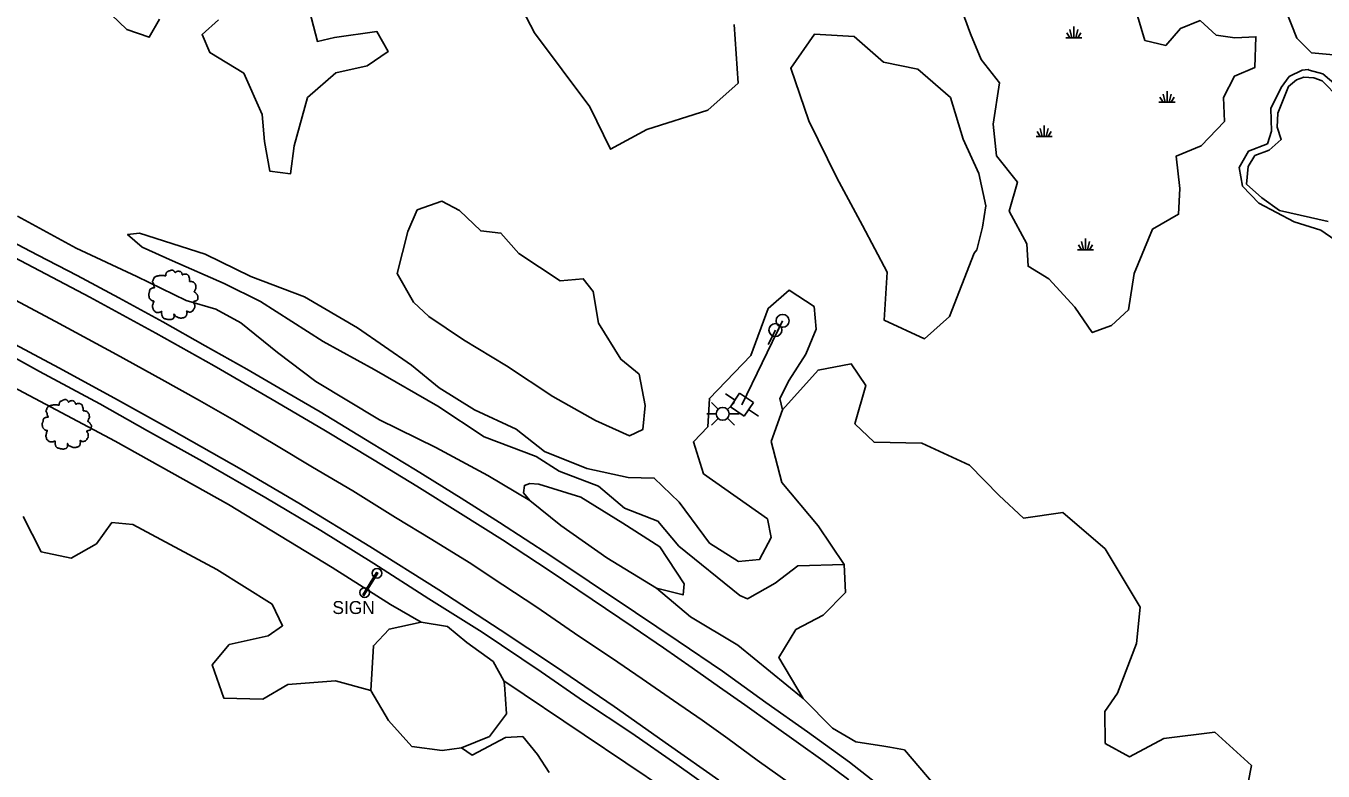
# Model space of a CAD drawing. Extents: x 2160437 to 2172832, y 205694 to 212444.
# Drawn here: x 2170821.8 to 2171222.4, y 207237.9 to 207468 of the extents above; entities that cross this region are included whole.
import ezdxf

# ---------------------------------------------------------------- set-up
doc = ezdxf.new("R2010")
doc.units = 0
for name, color, linetype in [('Default', 7, 'Continuous'), ('RD_EX_Bldg_Signs', 7, 'Continuous'), ('RD_EX_BldgApp_txCode', 7, 'Continuous'), ('RD_EX_H2O_Pond', 7, 'Continuous'), ('RD_EX_H2O_WetLd', 7, 'Continuous'), ('RD_EX_LaneStripe', 7, 'Continuous'), ('RD_EX_Road', 7, 'Continuous'), ('RD_EX_Road_Post', 7, 'Continuous'), ('RD_EX_UT', 7, 'Continuous'), ('RD_EX_UT_Guy', 7, 'Continuous'), ('RD_EX_VEG', 7, 'Continuous'), ('RD_EX_VEG_ShrubLine', 7, 'Continuous'), ('RD_EX_VEG_TreeLine', 7, 'Continuous')]:
    doc.layers.add(name, color=color, linetype=linetype)

# ---------------------------------------------------------------- blocks, each defined once
blk = doc.blocks.new('MARSH')
at = {"layer": 'Default'}
for points in [[(-0.0417, 0), (0.0417, 0)], [(-0.0365, 0.026), (-0.0208, 0)], [(-0.0104, 0), (-0.0208, 0.0417)], [(0, 0.0573), (0, 0)], [(0.0104, 0), (0.0208, 0.0417)], [(0.0365, 0.026), (0.0208, 0)]]:
    blk.add_lwpolyline(points, dxfattribs=at)
blk = doc.blocks.new('POST')
at = {"layer": 'Default'}
for start, end in [(90, 270), (270, 90)]:
    blk.add_arc((0, 0), 0.0417, start, end, dxfattribs=at)
blk = doc.blocks.new('T2')
at = {"layer": 'RD_EX_VEG'}
for points in [[(0.05, 7.21), (-0.25, 7.24), (-0.57, 7.14), (-0.82, 7.04), (-1.05, 6.96), (-1.27, 6.86), (-1.57, 6.69), (-1.8, 6.49), (-1.92, 6.24), (-1.97, 6.01), (-2.02, 5.74), (-2.02, 5.56), (-2.15, 5.54), (-2.3, 5.56), (-2.55, 5.64), (-2.8, 5.64), (-3.05, 5.64), (-3.4, 5.61), (-3.75, 5.61), (-4.02, 5.56), (-4.35, 5.51), (-4.72, 5.39), (-5.07, 5.26), (-5.37, 5.01), (-5.62, 4.54), (-5.75, 4.19), (-5.9, 3.94), (-5.75, 3.49), (-5.57, 3.14), (-5.55, 2.94), (-5.47, 2.52), (-5.37, 2.29), (-5.25, 2.09), (-5.32, 2.07), (-5.7, 2.02), (-6, 1.92), (-6.42, 1.69), (-6.64, 1.47), (-6.74, 1.14), (-6.77, 0.79), (-6.87, 0.59), (-6.94, 0.32), (-6.97, 0.24), (-7.02, -0.08), (-6.92, -0.53), (-6.89, -0.88), (-6.77, -1.11), (-6.62, -1.28), (-6.44, -1.53), (-6.05, -1.76), (-5.72, -1.86), (-5.52, -1.88), (-5.7, -2.38), (-5.75, -2.73), (-5.87, -3.13), (-5.87, -3.21), (-5.92, -3.68), (-5.77, -4.01), (-5.7, -4.38), (-5.52, -4.61), (-5.25, -4.91), (-4.92, -5.13), (-4.42, -5.26), (-4.02, -5.23), (-3.45, -5.06), (-3.2, -4.98), (-3.22, -5.16), (-3.2, -5.53), (-3.2, -5.96), (-3.05, -6.28), (-2.95, -6.56), (-2.8, -6.81), (-2.47, -7.03), (-2.07, -7.11), (-1.65, -7.26), (-1.2, -7.33), (-0.7, -7.36), (-0.1, -7.21), (0.18, -7.08), (0.28, -6.91), (0.48, -6.53), (0.43, -6.31), (0.45, -5.71), (0.55, -5.88), (0.73, -6.23), (1.23, -6.53), (1.63, -6.71), (2.1, -6.86), (2.4, -6.93), (2.88, -6.86), (3.25, -6.78), (3.63, -6.66), (3.93, -6.38), (4.1, -6.11), (4.15, -5.83), (4.23, -5.46), (4.28, -5.28)], [(4.28, -5.28), (4.2, -5.11), (4.15, -4.86), (4.23, -4.88), (4.4, -4.93), (4.68, -5.06), (4.9, -5.13), (5.23, -5.11), (5.5, -5.01), (5.95, -4.73), (6.22, -4.26), (6.5, -3.86), (6.57, -3.53), (6.52, -3.31), (6.5, -2.81), (6.3, -2.56), (6.25, -2.43), (6.15, -2.03), (6.22, -1.98), (6.5, -1.93), (6.87, -1.81), (7.15, -1.68), (7.37, -1.51), (7.45, -1.28), (7.42, -0.88), (7.47, -0.48), (7.4, -0.33), (7.3, -0.18), (7.22, 0.02), (7.07, 0.17), (6.97, 0.32), (6.87, 0.42), (6.75, 0.57), (6.57, 0.69), (6.42, 0.74), (6.37, 0.89), (6.52, 1.09), (6.57, 1.19), (6.6, 1.42), (6.82, 1.77), (6.87, 2.17), (6.82, 2.59), (6.77, 2.87), (6.62, 3.14), (6.42, 3.39), (6.3, 3.56), (6.12, 3.69), (5.8, 3.81), (5.55, 3.86), (5.2, 3.86), (5, 3.91), (5.03, 3.96), (5.03, 4.11), (5.03, 4.39), (4.95, 4.84), (4.8, 5.34), (4.8, 5.36), (4.7, 5.61), (4.48, 5.81), (4.3, 5.91), (4.1, 6.04), (3.85, 6.06), (3.55, 6.06), (3.28, 6.01), (3.08, 5.91), (2.9, 5.79), (2.83, 5.94), (2.73, 6.24), (2.68, 6.39), (2.53, 6.56), (2.3, 6.76), (1.85, 6.89), (1.23, 6.81), (0.93, 6.61), (0.78, 6.44), (0.73, 6.56), (0.53, 6.76), (0.43, 6.94), (0.25, 7.06), (0.1, 7.16), (0, 7.21)]]:
    blk.add_spline(points, degree=3, dxfattribs=at)
blk = doc.blocks.new('PP')
at = {"layer": 'RD_EX_UT'}
for p, q in [((2.49, 2.51), (-2.51, 2.51)), ((-2.51, 2.51), (-2.51, -2.49)), ((2.49, -2.49), (2.49, 2.51)), ((-5.94, -0.05), (-2.47, -0.05)), ((-2.51, -2.49), (2.49, -2.49)), ((2.42, -0.05), (6.06, -0.05))]:
    blk.add_line(p, q, dxfattribs=at)

msp = doc.modelspace()

# ---------------------------------------------------------------- linework, layer by layer
at = {"layer": 'RD_EX_Bldg_Signs'}
msp.add_lwpolyline([(2170925.78, 207292.33), (2170930.07, 207299.26), (2170930.43, 207299.03), (2170926.14, 207292.1)], close=True, dxfattribs=at)
at = {"layer": 'RD_EX_H2O_Pond'}
msp.add_lwpolyline([(2171223.91, 207407.61), (2171215.24, 207409.62), (2171208.89, 207411.01), (2171203.41, 207414.96), (2171198.75, 207419.15), (2171199.26, 207424.58), (2171201.33, 207427.96), (2171205.76, 207429.6), (2171209.43, 207432.91), (2171208.23, 207436.73), (2171208.42, 207441.03), (2171211.72, 207449.31), (2171214.19, 207451.34), (2171216.38, 207452.22), (2171219.54, 207451.99), (2171222.12, 207451.05), (2171227.31, 207445.7)], dxfattribs=at)
at = {"layer": 'RD_EX_H2O_WetLd'}
msp.add_lwpolyline([(2171165.1, 207471.1), (2171167.33, 207463.54), (2171173.77, 207462), (2171178.29, 207467.17), (2171184.43, 207469.65), (2171189.31, 207465.16), (2171195.14, 207464.31), (2171201.64, 207464.68), (2171201.24, 207455.17), (2171195.02, 207452.52), (2171191.58, 207445.94), (2171191.95, 207438.52), (2171184.72, 207431.03), (2171176.98, 207427.76), (2171178.13, 207417.84), (2171177.73, 207409.86), (2171169.7, 207405.28), (2171164, 207391.58), (2171162.29, 207380.32), (2171157.01, 207375.5), (2171151.1, 207373.32), (2171145.71, 207381.12), (2171137.63, 207389.94), (2171131.24, 207393.8), (2171130.85, 207400.72), (2171125.38, 207410.79), (2171127.96, 207419.71), (2171121.51, 207427.88), (2171120.49, 207437.64), (2171122.41, 207450.44), (2171116.74, 207457.64), (2171113.46, 207465.58), (2171110.54, 207473.66)], dxfattribs=at)
at = {"layer": 'RD_EX_LaneStripe'}
msp.add_lwpolyline([(2171057.86, 207233.96), (2171047.6, 207241.26), (2171038.51, 207247.92), (2171030.59, 207253.61), (2171021.8, 207259.72), (2171012.07, 207266.37), (2171002.66, 207272.85), (2170992.52, 207279.61), (2170979.54, 207288.55), (2170969.07, 207295.46), (2170958.61, 207302.27), (2170947.11, 207309.45), (2170935.95, 207316.25), (2170922.71, 207324.46), (2170910.32, 207331.8), (2170899.11, 207338.44), (2170886.22, 207346.19), (2170875.4, 207352.34), (2170863.78, 207358.8), (2170849.7, 207366.58), (2170830.89, 207376.77), (2170813.63, 207385.89)], dxfattribs=at)
at = {"layer": 'RD_EX_Road'}
for points in [[(2170808.45, 207406.07), (2170825.44, 207397.2), (2170837.58, 207390.92), (2170850.5, 207384.07), (2170864.02, 207376.63), (2170877.12, 207369.22), (2170889.95, 207362.01), (2170902.31, 207354.81), (2170912.64, 207348.83), (2170928.5, 207339.2), (2170942.09, 207330.88), (2170956.16, 207322.13), (2170968.04, 207314.62), (2170983.89, 207304.38), (2170995.75, 207296.45), (2171010.07, 207286.92), (2171023.21, 207277.99), (2171036.87, 207268.74), (2171050.24, 207259.11), (2171063.11, 207249.97), (2171076.1, 207240.67), (2171088.07, 207231.3)], [(2171075.94, 207235.22), (2171067.86, 207241.12), (2171060.32, 207246.47), (2171052.16, 207252.42), (2171043.77, 207258.41), (2171035.98, 207263.83), (2171027.56, 207269.77), (2171018.68, 207275.93), (2171009.33, 207282.38), (2170996.62, 207290.91), (2170983.36, 207299.8), (2170968.91, 207309.31), (2170955.96, 207317.49), (2170942.47, 207325.88), (2170929.31, 207333.95), (2170913.76, 207343.33), (2170897.77, 207352.68), (2170879.89, 207363.06), (2170861.87, 207373.14), (2170841.46, 207384.23), (2170826.06, 207392.41), (2170814.1, 207398.63)], [(2171037.38, 207229.55), (2171022.79, 207239.97), (2171008.84, 207249.58), (2170993.99, 207259.51), (2170980.86, 207268.51), (2170962.71, 207280.75), (2170946.19, 207291.09), (2170929.18, 207302.03), (2170912.88, 207312.19), (2170895.9, 207322.26), (2170876.18, 207333.58), (2170859.37, 207343.01), (2170844.59, 207351.26), (2170825.93, 207361.34), (2170810.8, 207369.66)], [(2171035.72, 207235.06), (2171020.23, 207246.05), (2171003.43, 207257.84), (2170985.33, 207270.23), (2170968.27, 207281.56), (2170949.32, 207293.83), (2170928.01, 207307.24), (2170906.06, 207320.59), (2170888.35, 207331.06), (2170866.72, 207343.32), (2170849.15, 207353.05), (2170831.97, 207362.41), (2170813.73, 207372.06)]]:
    msp.add_lwpolyline(points, dxfattribs=at)
at = {"layer": 'RD_EX_UT'}
for p, q in [((2171053.23, 207374.09), (2171051.02, 207369.6)), ((2171055.46, 207376.94), (2171053.26, 207372.45)), ((2171033.48, 207351.77), (2171035.58, 207349.68)), ((2171038.39, 207349.61), (2171040.56, 207351.77)), ((2171034.95, 207348.24), (2171032.02, 207348.24)), ((2171033.48, 207344.7), (2171035.56, 207346.78)), ((2171038.41, 207346.85), (2171040.56, 207344.7)), ((2171042.02, 207348.24), (2171038.95, 207348.24))]:
    msp.add_line(p, q, dxfattribs=at)
for centre in [(2171055.46, 207376.94), (2171053.23, 207374.09), (2171036.95, 207348.22)]:
    msp.add_circle(centre, 2, dxfattribs=at)
at = {"layer": 'RD_EX_UT_Guy'}
msp.add_lwpolyline([(2171055.46, 207376.94), (2171042.88, 207351.03)], dxfattribs=at)
at = {"layer": 'RD_EX_VEG_ShrubLine'}
for points in [[(2170843.29, 207476.3), (2170852.96, 207466.95), (2170859.84, 207464.5), (2170863.05, 207470.14)], [(2170881.27, 207469.94), (2170876.17, 207465.35), (2170878.56, 207459.76), (2170889.1, 207453.38), (2170894.69, 207440.69), (2170895.42, 207432.3), (2170897.12, 207423.14), (2170903.49, 207422.35), (2170904.62, 207431.02), (2170908.71, 207445.87), (2170917.43, 207453.5), (2170927.19, 207455.64), (2170933.62, 207460.07), (2170930.15, 207466.24), (2170917.1, 207464.41), (2170911.79, 207463.2), (2170911.79, 207463.2), (2170908.69, 207475.04)], [(2171228.44, 207447.99), (2171222.3, 207453.17), (2171218.09, 207454.34), (2171217.8, 207454.53), (2171215.89, 207454.38), (2171211.85, 207452.36), (2171209.39, 207449.01), (2171206.21, 207442.56), (2171206.46, 207435.56), (2171205.15, 207431.61), (2171199.31, 207429.35), (2171196.41, 207424.26), (2171197.44, 207418.53), (2171202.51, 207413.23), (2171213.42, 207407.55), (2171221.67, 207404.97), (2171226, 207401.96)], [(2170977.35, 207321.43), (2170964.45, 207329.21), (2170948.37, 207337.84), (2170931, 207346.34), (2170911.35, 207358.2), (2170899.49, 207367.13), (2170888.14, 207376.29), (2170880.39, 207380.52), (2170871.22, 207383.21), (2170856.06, 207390.65), (2170837.26, 207399.36), (2170819.16, 207409.27)], [(2171055.47, 207349.5), (2171054.58, 207352.91), (2171057.43, 207358.64), (2171062.65, 207366.65), (2171065.81, 207374.4), (2171065.23, 207381.35), (2171057.43, 207386.36), (2171050.98, 207380.76), (2171045.59, 207366.19), (2171032.87, 207352.97), (2171032.32, 207344.24), (2171027.91, 207339.53), (2171031.04, 207329.72), (2171050.74, 207315.75), (2171051.88, 207310.02), (2171048.36, 207303.27), (2171041.83, 207302.6), (2171032.9, 207308.24), (2171023.53, 207320.93), (2171015.82, 207328.36), (2171007.76, 207328.59), (2170995.02, 207331.3), (2170981.87, 207336.64), (2170973.18, 207343.5), (2170960.3, 207349.43), (2170949.37, 207356.3), (2170940.85, 207363.28), (2170924.22, 207374.82), (2170907.77, 207384.33), (2170891.27, 207390.61), (2170877.11, 207397.53), (2170856.82, 207404.02), (2170853.18, 207403.65), (2170857.7, 207399.73), (2170867.05, 207395.43), (2170883.04, 207388.47), (2170894.17, 207382.94), (2170913.57, 207370.54), (2170929.28, 207361.87), (2170948.98, 207350.56), (2170963.3, 207341.1), (2170979.3, 207335.06), (2170986.42, 207330.56), (2170998.56, 207325.89), (2171006.66, 207319.1), (2171016.95, 207315.07), (2171023.42, 207307.4), (2171042.21, 207292.12), (2171044.61, 207291.11), (2171053.16, 207295.95), (2171060.13, 207301.32), (2171074.51, 207301.74)], [(2170816.16, 207357.35), (2170849.29, 207339.83), (2170884.36, 207320.21), (2170916.34, 207300.79), (2170934.34, 207289.34), (2170943.81, 207283.92)], [(2170928.27, 207262.8), (2170917.39, 207265.77), (2170902.65, 207264.59), (2170894.96, 207260.07), (2170882.88, 207260.43), (2170879.27, 207270.76), (2170884.58, 207276.99), (2170896.61, 207279.62), (2170901.03, 207282.79), (2170897.79, 207289.49), (2170880.77, 207300.18), (2170854.81, 207314.08), (2170848.32, 207314.62), (2170843.59, 207308.12), (2170835.73, 207303.67), (2170826.5, 207305.58), (2170820.92, 207316.51)], [(2171061.77, 207260.34), (2171041.62, 207276.77), (2171026.99, 207285.55), (2171016.49, 207294.38)], [(2170969.33, 207265.74), (2170994.22, 207249.07), (2171019.95, 207231.81), (2171057.1, 207204.29), (2171086.49, 207181.68), (2171124.11, 207152.31), (2171171.23, 207114.4), (2171189.11, 207100.25), (2171205.42, 207087.84)], [(2170983.36, 207237.51), (2170979.78, 207243.04), (2170975.2, 207248.62), (2170969.86, 207248.32), (2170959.58, 207242.83), (2170956.26, 207245.11)]]:
    msp.add_lwpolyline(points, dxfattribs=at)
msp.add_lwpolyline([(2170936.45, 207391.56), (2170941.47, 207382.72), (2170946.17, 207378.26), (2170956.86, 207371.1), (2170970.18, 207363.02), (2170984.51, 207353.57), (2170997.65, 207346.19), (2171008.21, 207341.41), (2171012.29, 207343.41), (2171013.05, 207350.82), (2171011.16, 207360.46), (2171005.54, 207365.09), (2170998.63, 207376.24), (2170996.99, 207385.98), (2170993.91, 207389.94), (2170986.8, 207389.34), (2170974.04, 207397.77), (2170968.44, 207404.02), (2170962.24, 207404.73), (2170955.65, 207411.03), (2170950.23, 207413.94), (2170942.63, 207411.17), (2170939.68, 207404.56)], close=True, dxfattribs=at)
at = {"layer": 'RD_EX_VEG_TreeLine'}
for points in [[(2171040.52, 207468.48), (2171041.77, 207450.35), (2171032.41, 207442), (2171013.52, 207436), (2171002.35, 207429.92), (2170995.95, 207443.07), (2170978.87, 207465.84), (2170963.84, 207494.81)], [(2171112.04, 207222.22), (2171093.07, 207244.46), (2171088.56, 207245.32), (2171086.73, 207245.59), (2171078.05, 207246.93), (2171070.82, 207251.18), (2171061.77, 207260.34), (2171054.32, 207272.96), (2171059.51, 207281.59), (2171068, 207286.06), (2171074.87, 207293), (2171074.51, 207301.74), (2171066.41, 207313.64), (2171055.23, 207327.05), (2171051.96, 207339.68), (2171055.47, 207349.5), (2171066.4, 207361.72), (2171076.67, 207363.62), (2171081.15, 207356.97), (2171077.76, 207345.16), (2171083.71, 207339.46), (2171098.49, 207339.19), (2171113.19, 207332.32), (2171122.36, 207322.99), (2171129.89, 207316.05), (2171141.99, 207317.73), (2171155.09, 207306.49), (2171165.86, 207288.48), (2171164.78, 207277.26), (2171158.84, 207261.93), (2171155, 207256.25), (2171155.07, 207246.42), (2171162.58, 207242.34), (2171173.15, 207247.99), (2171188.97, 207249.9), (2171200.24, 207239.66), (2171198.12, 207228.59)]]:
    msp.add_lwpolyline(points, dxfattribs=at)
for points in [[(2171232.53, 207465.24), (2171226.68, 207458.95), (2171218.77, 207459.74), (2171214.23, 207464.28), (2171210.71, 207473.04), (2171213.77, 207479.7), (2171219.36, 207482.74), (2171224.84, 207481.34), (2171228.31, 207478.01), (2171230.37, 207474.3), (2171232.59, 207468.68), (2171232.58, 207466.24)], [(2171114.56, 207397.85), (2171106.98, 207378.27), (2171099.32, 207371.39), (2171086.85, 207377.13), (2171087.78, 207392.01), (2171080.1, 207406.37), (2171072.16, 207421.05), (2171063.55, 207438.69), (2171057.97, 207454.94), (2171065.26, 207465.46), (2171077.57, 207464.7), (2171086.61, 207456.86), (2171097.22, 207454.62), (2171107.29, 207445.9), (2171111.19, 207433.09), (2171116.09, 207422.46), (2171118.24, 207412.49), (2171117.21, 207405.82), (2171115.44, 207398.87)], [(2170980.15, 207326.53), (2170993.18, 207322.47), (2171006.14, 207314.46), (2171017.57, 207307.15), (2171025.07, 207295.74), (2171024.73, 207292.32), (2171016.49, 207294.38), (2171001.21, 207303.77), (2170987.01, 207313.71), (2170977.35, 207321.43), (2170975.42, 207323.87), (2170975.74, 207326.13), (2170977.42, 207326.68)], [(2170969.53, 207264.62), (2170970.15, 207255.56), (2170964.9, 207248.58), (2170956.26, 207245.11), (2170950.35, 207244.26), (2170940.94, 207245.53), (2170933.79, 207253.52), (2170928.27, 207262.8), (2170929.11, 207276.6), (2170933.92, 207281.73), (2170943.81, 207283.92), (2170951.94, 207282.52), (2170957.95, 207277.61), (2170966.06, 207271.73), (2170969.33, 207265.74)]]:
    msp.add_lwpolyline(points, close=True, dxfattribs=at)

# ---------------------------------------------------------------- block references
at = {"layer": 'RD_EX_H2O_WetLd', "xscale": 60, "yscale": 60}
for p in [(2171145.37, 207464.36), (2171174.18, 207444.46), (2171136.23, 207433.86), (2171149.01, 207398.89)]:
    msp.add_blockref('MARSH', p, dxfattribs=at)
at = {"layer": 'RD_EX_Road_Post', "xscale": 36, "yscale": 36}
for p in [(2170930.22, 207299), (2170926.41, 207293.03)]:
    msp.add_blockref('POST', p, dxfattribs=at)
at = {"layer": 'RD_EX_UT', "xscale": 1.02, "yscale": 1.0199999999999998, "rotation": -34.033832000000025}
msp.add_blockref('PP', (2171042.88, 207351.03), dxfattribs=at)
at = {"layer": 'RD_EX_VEG', "xscale": 1.0499999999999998, "yscale": 1.0499999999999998}
for p in [(2170867.06, 207385.03), (2170834.16, 207345.06)]:
    msp.add_blockref('T2', p, dxfattribs=at)

# ---------------------------------------------------------------- texts
at = {"layer": 'RD_EX_BldgApp_txCode'}
msp.add_text('SIGN', height=4, dxfattribs=at).set_placement((2170916.43, 207286.41))

doc.saveas('drawing.dxf')
